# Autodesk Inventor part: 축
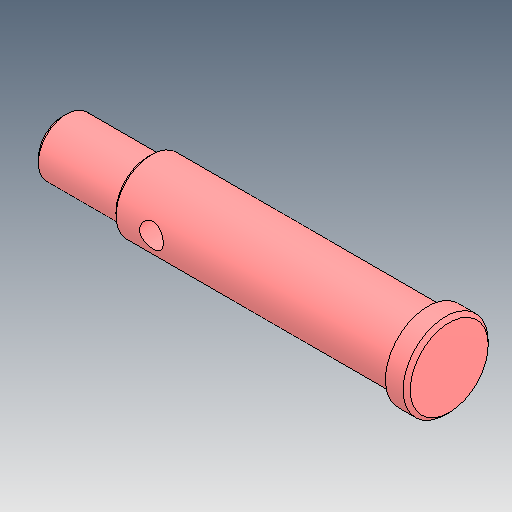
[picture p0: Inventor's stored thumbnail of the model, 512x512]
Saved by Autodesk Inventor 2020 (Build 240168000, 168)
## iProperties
Created: 2025-01
Part Number: 축
Material: 강철, 탄소
Document SubType Name: Modeling
Designer: 1강의실14
Density: 7.85 g/cm^3
Appearance: 기본값
Author: jhkim
Sending System: Autodesk Inventor 2025
Preprocessor: ST-DEVELOPER v20
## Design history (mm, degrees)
feature "솔리드1"
node "솔리드2"
